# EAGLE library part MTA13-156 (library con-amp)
AMP connector
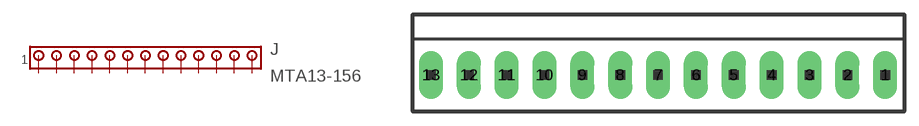
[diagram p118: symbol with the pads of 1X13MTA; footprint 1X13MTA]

Designator prefix J

## MTA13-156 (OC_FARNELL: unknown; OC_NEWARK: unknown)  [1X13MTA]
1  1  pas
2  2  pas
3  3  pas
4  4  pas
5  5  pas
6  6  pas
7  7  pas
8  8  pas
9  9  pas
10  10  pas
11  11  pas
12  12  pas
13  13  pas

## Footprint 1X13MTA (pad centres in mm)
AMP MTA connector
drill 1.676 long: 1 23.774,0; 2 19.812,0; 3 15.85,0; 4 11.887,0; 5 7.925,0; 6 3.962,0; 7 0,0; 8 -3.962,0; 9 -7.925,0; 10 -11.887,0; 11 -15.85,0; 12 -19.812,0; 13 -23.774,0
